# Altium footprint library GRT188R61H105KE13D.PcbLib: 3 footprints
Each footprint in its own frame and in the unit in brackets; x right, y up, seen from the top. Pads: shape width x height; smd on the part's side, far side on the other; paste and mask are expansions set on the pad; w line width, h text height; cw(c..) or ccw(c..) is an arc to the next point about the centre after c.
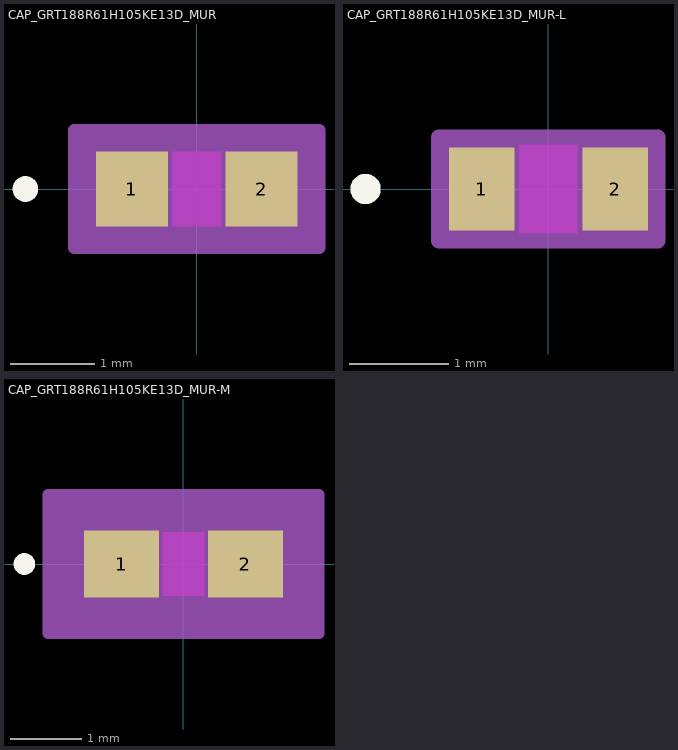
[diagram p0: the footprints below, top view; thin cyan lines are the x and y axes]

## CAP_GRT188R61H105KE13D_MUR [mil]
pads (2):
  rect 33.78x35 smd paste+0 mask+0: 1(-30.39,0) 2(30.39,0)
Top Layer keep-out:
  region: -11.5,-15.5 -11.5,15.5 11.5,15.5 11.5,-15.5
Top Overlay:
  circle w6: c-80.28,0 r3
  text ".Designator" at -137.5,-25 h50
Keep-Out Layer:
  region: -11.5,-17.5 -11.5,17.5 11.5,17.5 11.5,-17.5
Mechanical 13:
  circle w1: c-25.39,0 r3
  lines w1: -33.5,-17.5 -33.5,17.5 ; -33.5,-17.5 -13.5,-17.5 -13.5,17.5 -33.5,17.5 ; -33.5,-17.5 33.5,-17.5 ; -33.5,-17.5 -33.5,17.5 ; -33.5,17.5 33.5,17.5 ; 33.5,-17.5 13.5,-17.5 13.5,17.5 33.5,17.5 ; 33.5,-17.5 33.5,17.5 ; 33.5,-17.5 33.5,17.5
  text ".Designator" at -137.5,-25 h50
Mechanical 15:
  region: 57.28,-27.5 -57.28,-27.5 -57.28,27.5 57.28,27.5
  lines w6: -57.28,-27.5 -57.28,27.5 57.28,27.5 57.28,-27.5 -57.28,-27.5
3D body "CAP_GRT188R61H105KE13D_MUR.step": height 35, standoff 0, extent -33.5,-17.48 33.5,17.48

## CAP_GRT188R61H105KE13D_MUR-L [mil]
pads (2):
  rect 25.91x33.03 smd paste+0 mask+0: 1(-26.45,0) 2(26.45,0)
Top Layer keep-out:
  region: -11.5,-15.5 -11.5,15.5 11.5,15.5 11.5,-15.5
Top Overlay:
  circle w6: c-72.41,0 r3
  text ".Designator" at -137.5,-25 h50
Keep-Out Layer:
  region: -11.5,-17.5 -11.5,17.5 11.5,17.5 11.5,-17.5
Mechanical 13:
  circle w1: c-21.45,0 r3
  lines w1: -33.5,-17.5 -33.5,17.5 ; -33.5,-17.5 -13.5,-17.5 -13.5,17.5 -33.5,17.5 ; -33.5,-17.5 33.5,-17.5 ; -33.5,-17.5 -33.5,17.5 ; -33.5,17.5 33.5,17.5 ; 33.5,-17.5 13.5,-17.5 13.5,17.5 33.5,17.5 ; 33.5,-17.5 33.5,17.5 ; 33.5,-17.5 33.5,17.5
  text ".Designator" at -137.5,-25 h50
Mechanical 15:
  region: 43.41,-20.52 -43.41,-20.52 -43.41,20.52 43.41,20.52
  lines w6: -43.41,-20.52 -43.41,20.52 43.41,20.52 43.41,-20.52 -43.41,-20.52
3D body "CAP_GRT188R61H105KE13D_MUR.step": height 35, standoff 0, extent -33.5,-17.48 33.5,17.48

## CAP_GRT188R61H105KE13D_MUR-M [mil]
pads (2):
  rect 41.65x36.97 smd paste+0 mask+0: 1(-34.33,0) 2(34.33,0)
Top Layer keep-out:
  region: -11.5,-15.5 -11.5,15.5 11.5,15.5 11.5,-15.5
Top Overlay:
  circle w6: c-88.15,0 r3
  text ".Designator" at -137.5,-25 h50
Keep-Out Layer:
  region: -11.5,-17.5 -11.5,17.5 11.5,17.5 11.5,-17.5
Mechanical 13:
  circle w1: c-29.33,0 r3
  lines w1: -33.5,-17.5 -33.5,17.5 ; -33.5,-17.5 -13.5,-17.5 -13.5,17.5 -33.5,17.5 ; -33.5,-17.5 33.5,-17.5 ; -33.5,-17.5 -33.5,17.5 ; -33.5,17.5 33.5,17.5 ; 33.5,-17.5 13.5,-17.5 13.5,17.5 33.5,17.5 ; 33.5,-17.5 33.5,17.5 ; 33.5,-17.5 33.5,17.5
  text ".Designator" at -137.5,-25 h50
Mechanical 15:
  region: 75.15,-38.48 -75.15,-38.48 -75.15,38.48 75.15,38.48
  lines w6: -75.15,-38.48 -75.15,38.48 75.15,38.48 75.15,-38.48 -75.15,-38.48
3D body "CAP_GRT188R61H105KE13D_MUR.step": height 35, standoff 0, extent -33.5,-17.48 33.5,17.48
